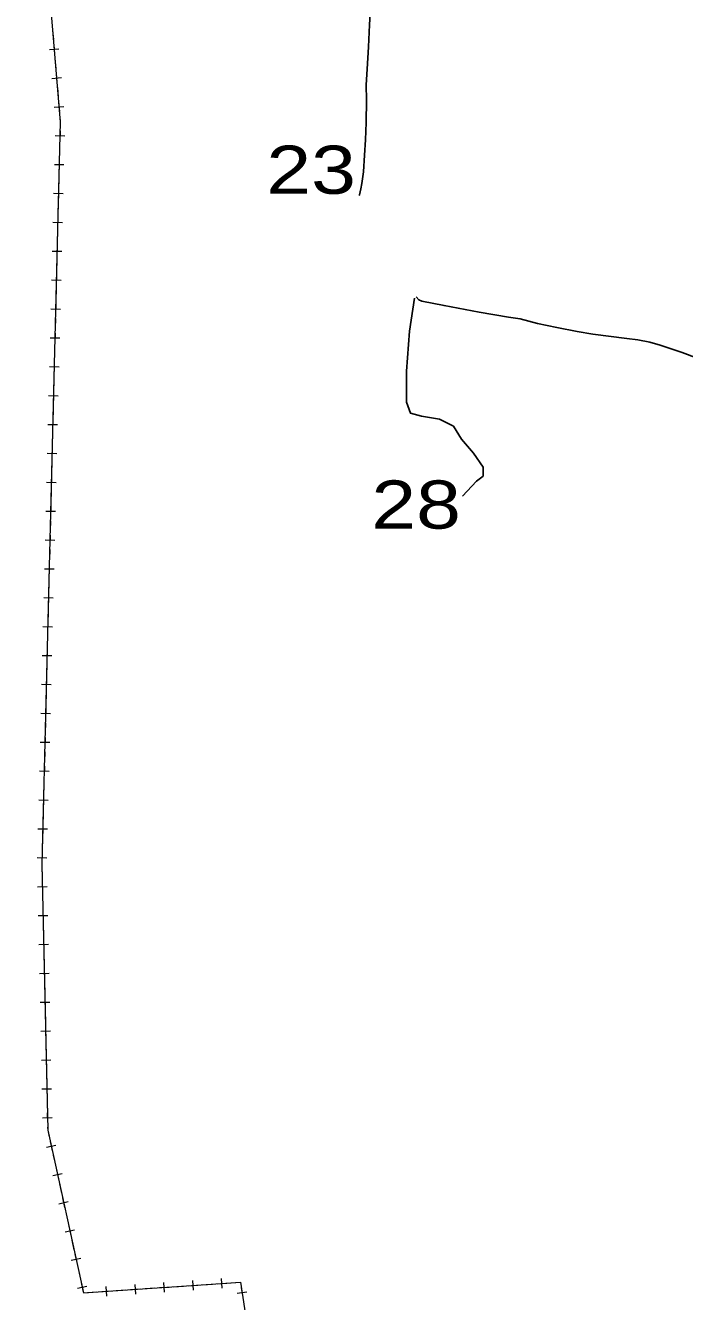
# Model space of a CAD drawing. Extents: x 476989 to 498418, y 4381813 to 4416555.
# Drawn here: x 483851 to 484535, y 4385812 to 4387137 of the extents above; entities that cross this region are included whole.
import ezdxf
from ezdxf.enums import TextEntityAlignment as Align

# ---------------------------------------------------------------- set-up
doc = ezdxf.new("R2010")
doc.units = 0
doc.header["$LTSCALE"] = 20
for name, color, linetype, lineweight in [('13', 7, 'Continuous', 13), ('34', 7, 'Continuous', 13), ('6', 7, 'Continuous', 25)]:
    doc.layers.add(name, color=color, linetype=linetype, lineweight=lineweight)

msp = doc.modelspace()

# ---------------------------------------------------------------- linework, layer by layer
at = {"layer": '34'}
for p, q in [((483879.05, 4387132.21), (483879.88, 4387122.24)), ((483875.73, 4387111.86), (483885.7, 4387112.69)), ((483880.3, 4387117.26), (483881.13, 4387107.29)), ((483881.54, 4387102.31), (483882.38, 4387092.35)), ((483882.79, 4387087.36), (483883.63, 4387077.4)), ((483878.23, 4387081.96), (483888.19, 4387082.8)), ((483884.04, 4387072.41), (483884.87, 4387062.45)), ((483880.72, 4387052.07), (483890.69, 4387052.9)), ((483885.29, 4387057.47), (483886.12, 4387047.5)), ((483881.65, 4387022.67), (483891.64, 4387022.42)), ((483886.77, 4387027.54), (483886.52, 4387017.54)), ((483886.4, 4387012.55), (483886.15, 4387002.55)), ((483880.91, 4386992.67), (483890.9, 4386992.43)), ((483886.03, 4386997.55), (483885.78, 4386987.55)), ((483885.66, 4386982.55), (483885.41, 4386972.56)), ((483885.29, 4386967.56), (483885.04, 4386957.56)), ((483880.17, 4386962.68), (483890.16, 4386962.44)), ((483884.92, 4386952.56), (483884.67, 4386942.57)), ((483879.43, 4386932.69), (483889.42, 4386932.45)), ((483884.55, 4386937.57), (483884.3, 4386927.57)), ((483884.18, 4386922.57), (483883.93, 4386912.58)), ((483878.69, 4386902.7), (483888.69, 4386902.46)), ((483883.81, 4386907.58), (483883.56, 4386897.58)), ((483883.44, 4386892.58), (483883.19, 4386882.58)), ((483883.07, 4386877.59), (483882.83, 4386867.59)), ((483877.95, 4386872.71), (483887.95, 4386872.46)), ((483882.7, 4386862.59), (483882.46, 4386852.59)), ((483882.33, 4386847.6), (483882.09, 4386837.6)), ((483877.21, 4386842.72), (483887.21, 4386842.47)), ((483881.96, 4386832.6), (483881.72, 4386822.6)), ((483876.47, 4386812.73), (483886.47, 4386812.48)), ((483881.59, 4386817.6), (483881.35, 4386807.61)), ((483881.22, 4386802.61), (483880.98, 4386792.61)), ((483875.73, 4386782.74), (483885.73, 4386782.49)), ((483880.85, 4386787.61), (483880.61, 4386777.62)), ((483880.48, 4386772.62), (483880.24, 4386762.62)), ((483880.12, 4386757.62), (483879.87, 4386747.63)), ((483874.99, 4386752.75), (483884.99, 4386752.5)), ((483879.75, 4386742.63), (483879.5, 4386732.63)), ((483879.38, 4386727.63), (483879.13, 4386717.64)), ((483874.25, 4386722.76), (483884.25, 4386722.51)), ((483879.01, 4386712.64), (483878.76, 4386702.64)), ((483873.52, 4386692.77), (483883.51, 4386692.52)), ((483878.64, 4386697.64), (483878.39, 4386687.64)), ((483878.27, 4386682.65), (483878.02, 4386672.65)), ((483872.78, 4386662.77), (483882.77, 4386662.53)), ((483877.9, 4386667.65), (483877.65, 4386657.65)), ((483877.53, 4386652.65), (483877.28, 4386642.66)), ((483877.16, 4386637.66), (483876.91, 4386627.66)), ((483872.04, 4386632.78), (483882.03, 4386632.54)), ((483876.79, 4386622.66), (483876.54, 4386612.67)), ((483871.3, 4386602.79), (483881.3, 4386602.55)), ((483876.42, 4386607.67), (483876.17, 4386597.67)), ((483876.05, 4386592.67), (483875.8, 4386582.68)), ((483870.56, 4386572.8), (483880.56, 4386572.56)), ((483875.68, 4386577.68), (483875.43, 4386567.68)), ((483875.31, 4386562.68), (483875.06, 4386552.69)), ((483869.82, 4386542.81), (483879.82, 4386542.56)), ((483874.94, 4386547.69), (483874.7, 4386537.69)), ((483874.57, 4386532.69), (483874.33, 4386522.69)), ((483874.2, 4386517.7), (483873.96, 4386507.7)), ((483869.08, 4386512.82), (483879.08, 4386512.57)), ((483873.83, 4386502.7), (483873.59, 4386492.7)), ((483868.34, 4386482.83), (483878.34, 4386482.58)), ((483873.46, 4386487.7), (483873.22, 4386477.71)), ((483873.09, 4386472.71), (483872.85, 4386462.71)), ((483867.6, 4386452.84), (483877.6, 4386452.59)), ((483872.72, 4386457.71), (483872.5, 4386448.65)), ((483872.35, 4386442.72), (483872.11, 4386432.72)), ((483872.5, 4386448.65), (483872.48, 4386447.72)), ((483866.86, 4386422.85), (483876.86, 4386422.6)), ((483871.99, 4386427.72), (483871.74, 4386417.73)), ((483871.62, 4386412.73), (483871.37, 4386402.73)), ((483871.25, 4386397.73), (483871, 4386387.74)), ((483866.12, 4386392.86), (483876.12, 4386392.61)), ((483870.88, 4386382.74), (483870.63, 4386372.74)), ((483865.39, 4386362.87), (483875.38, 4386362.62)), ((483870.51, 4386367.74), (483870.26, 4386357.74)), ((483870.14, 4386352.75), (483869.89, 4386342.75)), ((483864.65, 4386332.88), (483874.64, 4386332.63)), ((483869.77, 4386337.75), (483869.52, 4386327.75)), ((483869.4, 4386322.75), (483869.15, 4386312.76)), ((483869.03, 4386307.76), (483868.78, 4386297.76)), ((483863.91, 4386302.88), (483873.9, 4386302.64)), ((483868.66, 4386292.76), (483868.41, 4386282.77)), ((483868.29, 4386277.77), (483868.04, 4386267.77)), ((483863.17, 4386272.89), (483873.17, 4386272.65)), ((483868.07, 4386262.77), (483868.29, 4386252.78)), ((483863.51, 4386242.67), (483873.5, 4386242.89)), ((483868.4, 4386247.78), (483868.61, 4386237.78)), ((483868.72, 4386232.78), (483868.94, 4386222.78)), ((483864.16, 4386212.68), (483874.16, 4386212.89)), ((483869.05, 4386217.78), (483869.27, 4386207.79)), ((483869.37, 4386202.79), (483869.59, 4386192.79)), ((483869.7, 4386187.79), (483869.92, 4386177.79)), ((483864.81, 4386182.68), (483874.81, 4386182.9)), ((483870.03, 4386172.79), (483870.24, 4386162.8)), ((483870.35, 4386157.8), (483870.57, 4386147.8)), ((483865.46, 4386152.69), (483875.46, 4386152.91)), ((483870.68, 4386142.8), (483870.9, 4386132.8)), ((483866.11, 4386122.7), (483876.11, 4386122.91)), ((483871, 4386127.8), (483871.22, 4386117.81)), ((483871.33, 4386112.81), (483871.55, 4386102.81)), ((483866.77, 4386092.7), (483876.76, 4386092.92)), ((483871.66, 4386097.81), (483871.87, 4386087.81)), ((483871.98, 4386082.82), (483872.2, 4386072.82)), ((483872.31, 4386067.82), (483872.53, 4386057.82)), ((483867.42, 4386062.71), (483877.42, 4386062.93)), ((483872.63, 4386052.82), (483872.85, 4386042.82)), ((483868.07, 4386032.72), (483878.07, 4386032.94)), ((483872.96, 4386037.83), (483873.18, 4386027.83)), ((483873.29, 4386022.83), (483873.5, 4386012.83)), ((483868.72, 4386002.73), (483878.72, 4386002.94)), ((483873.61, 4386007.83), (483873.83, 4385997.84)), ((483872.79, 4385972.17), (483882.55, 4385974.3)), ((483876.6, 4385978.12), (483878.74, 4385968.35)), ((483879.81, 4385963.47), (483881.95, 4385953.7)), ((483883.02, 4385948.81), (483885.16, 4385939.04)), ((483879.2, 4385942.86), (483888.97, 4385945)), ((483886.23, 4385934.16), (483888.36, 4385924.39)), ((483889.43, 4385919.51), (483891.57, 4385909.74)), ((483885.62, 4385913.55), (483895.39, 4385915.69)), ((483892.64, 4385904.85), (483894.78, 4385895.09)), ((483892.03, 4385884.25), (483901.8, 4385886.39)), ((483895.85, 4385890.2), (483897.99, 4385880.43)), ((483899.06, 4385875.55), (483901.2, 4385865.78)), ((483898.45, 4385854.94), (483908.22, 4385857.08)), ((483902.27, 4385860.9), (483904.4, 4385851.13)), ((483905.47, 4385846.24), (483907.61, 4385836.47)), ((483904.87, 4385825.64), (483914.64, 4385827.77)), ((483908.68, 4385831.59), (483910.82, 4385821.82)), ((483935.44, 4385817.64), (483934.77, 4385827.62)), ((483965.37, 4385819.66), (483964.7, 4385829.64)), ((483989.98, 4385826.33), (483999.96, 4385827)), ((483995.31, 4385821.68), (483994.63, 4385831.66)), ((484004.95, 4385827.34), (484014.92, 4385828.01)), ((484019.91, 4385828.35), (484029.89, 4385829.02)), ((484025.24, 4385823.7), (484024.56, 4385833.68)), ((484034.88, 4385829.36), (484044.86, 4385830.03)), ((484049.84, 4385830.37), (484059.82, 4385831.04)), ((484055.17, 4385825.72), (484054.5, 4385835.7)), ((483915.15, 4385821.28), (483925.13, 4385821.95)), ((483930.12, 4385822.29), (483940.09, 4385822.96)), ((483945.08, 4385823.3), (483955.06, 4385823.97)), ((483960.05, 4385824.31), (483970.03, 4385824.98)), ((483975.01, 4385825.32), (483984.99, 4385825.99)), ((484070.7, 4385820.58), (484080.58, 4385822.1)), ((484074.88, 4385826.28), (484076.4, 4385816.39))]:
    msp.add_line(p, q, dxfattribs=at)
for points in [[(484108, 4387807), (483853, 4387811), (483851, 4387468), (483887, 4387037), (483872.5, 4386448.65)], [(483886.54, 4387042.52), (483887, 4387037), (483886.89, 4387032.54)], [(483872.5, 4386448.65), (483868, 4386266), (483874, 4385990), (483911, 4385821), (484074, 4385832), (484088, 4385741), (483902, 4385569), (484007, 4385465), (484103, 4385395), (484103.22, 4385394.84)], [(483873.94, 4385992.84), (483874, 4385990), (483875.53, 4385983)], [(484064.81, 4385831.38), (484074, 4385832), (484074.12, 4385831.22)]]:
    msp.add_lwpolyline(points, dxfattribs=at)
at = {"layer": '6'}
for points in [[(484212.82, 4387295.28), (484212.47, 4387278.4), (484211.44, 4387240.58), (484210.65, 4387220.54), (484209.3, 4387209.89), (484208.08, 4387198.84), (484207.98, 4387189.84), (484208.12, 4387179.31), (484208.42, 4387167.67), (484208.7, 4387158.03), (484208.44, 4387149.25), (484207.87, 4387137.58), (484207.04, 4387114.72), (484205.45, 4387091.7), (484204.57, 4387075.39), (484204.95, 4387059.47), (484204.36, 4387036.27), (484203.86, 4387018.17), (484202.77, 4387002.21), (484201.65, 4386984.79), (484200.05, 4386972.86), (484199.05, 4386967.22), (484197.58, 4386960.92), (484197.34, 4386960.26)], [(484254.56, 4386853.9), (484249.39, 4386819.63), (484246.28, 4386778.08), (484246.28, 4386745.88), (484250.42, 4386734.46), (484261.81, 4386731.34), (484280.45, 4386728.23), (484294.94, 4386720.96), (484303.23, 4386707.45), (484315.65, 4386692.91), (484326, 4386678.37), (484326, 4386669.03), (484318.76, 4386663.83), (484304.26, 4386648.25)], [(484256.33, 4386855.02), (484259.2, 4386852.12), (484262.08, 4386850.81), (484285.37, 4386846.1), (484321.78, 4386839.14), (484351.99, 4386834.18), (484364.12, 4386832.42), (484382.29, 4386827.59), (484402.33, 4386823.45), (484423.29, 4386819.3), (484439.77, 4386816.4), (484475.05, 4386811.94), (484486.31, 4386810.65), (484498.67, 4386808.05), (484509.39, 4386804.9), (484532.44, 4386797.25), (484547.84, 4386791.37)]]:
    msp.add_lwpolyline(points, dxfattribs=at)

# ---------------------------------------------------------------- texts
at = {"layer": '13', "width": 1.25}
for s, p in [('23', (484147.37, 4386962.13)), ('28', (484256.27, 4386614.47))]:
    msp.add_text(s, height=50, dxfattribs=at).set_placement(p, align=Align.CENTER)

doc.saveas('drawing.dxf')
